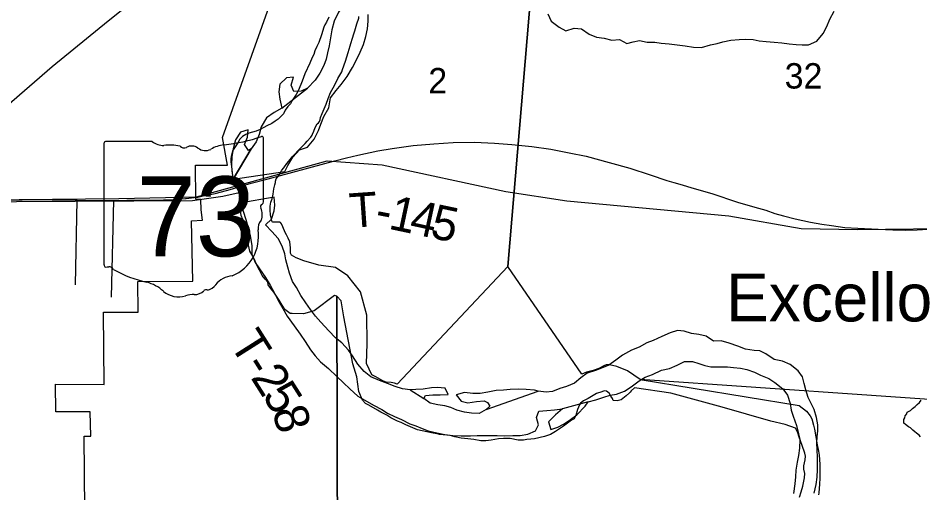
# Model space of a CAD drawing. Extents: x 0 to 34, y 0 to 22.
# Drawn here: x 3.596 to 5.086, y 14.655 to 15.439 of the extents above; entities that cross this region are included whole.
import ezdxf

# ---------------------------------------------------------------- set-up
doc = ezdxf.new("R2010")
doc.units = 0
for name, color, linetype in [('GM_X_City_Street', 7, 'Continuous'), ('GM_X_Corporation', 7, 'Continuous'), ('GM_X_Major_River', 7, 'Continuous'), ('GM_X_Minor_Lake', 7, 'Continuous'), ('GM_X_Minor_River', 7, 'Continuous'), ('GM_X_Rail_Line', 7, 'Continuous'), ('GM_X_Section_Text', 7, 'Continuous'), ('GM_X_State_Location', 7, 'Continuous'), ('GM_X_State_Route', 7, 'Continuous'), ('GM_X_State_Shield', 7, 'Continuous'), ('GM_X_Township_Road_Text', 7, 'Continuous'), ('GM_X_Unincorporated_Text', 7, 'Continuous')]:
    doc.layers.add(name, color=color, linetype=linetype)

msp = doc.modelspace()

# ---------------------------------------------------------------- linework, layer by layer
at = {"layer": 'GM_X_City_Street'}
for p, q in [((3.6909, 14.9987), (3.6938, 15.1382)), ((3.7507, 14.9784), (3.7543, 15.1377))]:
    msp.add_line(p, q, dxfattribs=at)
at = {"layer": 'GM_X_Corporation'}
for points in [[(4.4791, 15.9012), (4.4054, 15.0286), (4.2225, 14.8344), (4.218, 14.8364), (4.2127, 14.8373), (4.2044, 14.8382), (4.1987, 14.8402), (4.1875, 14.8465), (4.1808, 14.8501), (4.1717, 14.8688), (4.1731, 14.901), (4.1727, 14.9487), (4.1621, 14.9872), (4.1411, 15.0134), (4.1209, 15.0271), (4.093, 15.0311), (4.0681, 15.0381), (4.0558, 15.0429), (4.0479, 15.0473), (4.0461, 15.0507), (4.0463, 15.0598), (4.045, 15.0697), (4.0424, 15.0754), (4.0395, 15.0808), (4.0373, 15.085), (4.0338, 15.0945), (4.0312, 15.0991), (4.0297, 15.1014), (4.0286, 15.1022), (4.0275, 15.1022), (4.0233, 15.102), (4.0199, 15.1017), (4.0169, 15.1017), (4.0161, 15.1025), (4.0147, 15.1067), (4.0133, 15.1139), (4.0127, 15.1215), (4.0125, 15.1283), (4.0138, 15.1347), (4.0158, 15.1404), (4.0175, 15.1483), (4.0188, 15.157), (4.0205, 15.1634), (4.0213, 15.1672), (4.0217, 15.1698), (4.0229, 15.1732), (4.0272, 15.1791), (4.032, 15.1878), (4.0355, 15.1915), (4.0405, 15.1986), (4.046, 15.2053), (4.0491, 15.2097), (4.0518, 15.2123), (4.0604, 15.2216), (4.0708, 15.2316), (4.0739, 15.2357), (4.0797, 15.2424), (4.0821, 15.2454), (4.0829, 15.2473), (4.0849, 15.2518), (4.0873, 15.2582), (4.0904, 15.2641), (4.0927, 15.266), (4.0943, 15.2682), (4.0951, 15.2705), (4.096, 15.2746), (4.0984, 15.281), (4.1051, 15.2964), (4.1084, 15.3058), (4.1124, 15.3156), (4.1167, 15.3238), (4.1199, 15.3298), (4.1246, 15.3388), (4.1309, 15.35), (4.1325, 15.3538), (4.1374, 15.3673), (4.1418, 15.382), (4.1447, 15.3929), (4.1459, 15.3967), (4.1488, 15.4057), (4.1508, 15.4128), (4.1524, 15.4174), (4.1561, 15.429), (4.159, 15.4384), (4.1594, 15.4411)], [(2.1072, 14.098), (3.6049, 14.098), (3.6045, 14.5716), (3.634, 14.5656), (3.707, 14.5657), (3.7055, 14.7489), (3.7162, 14.7489), (3.7154, 14.7888), (3.6586, 14.7888), (3.6582, 14.8349), (3.7385, 14.8339), (3.7375, 14.9532), (3.7944, 14.9533), (3.7943, 15.0043), (3.8851, 15.0045), (3.883, 15.1039), (3.901, 15.1054), (3.8988, 15.1225), (3.8983, 15.1392), (3.8899, 15.1397), (3.8896, 15.1958), (3.9423, 15.1962), (3.9341, 15.2418), (4.0311, 15.5141)], [(4.1098, 15.4402), (4.1058, 15.432), (4.103, 15.4275), (4.1014, 15.4234), (4.0978, 15.411), (4.0929, 15.3986), (4.0901, 15.3918), (4.0866, 15.3847), (4.0846, 15.3787), (4.0822, 15.3734), (4.0782, 15.3644), (4.0699, 15.3464), (4.0654, 15.3344), (4.0594, 15.3197), (4.0559, 15.3126), (4.0492, 15.3029), (4.0461, 15.2973), (4.0418, 15.2928), (4.0375, 15.2865), (4.0347, 15.2805), (4.0305, 15.276), (4.0258, 15.2716), (4.0208, 15.2687), (4.0154, 15.2646), (4.0074, 15.2606), (3.9963, 15.2548), (3.9898, 15.2519), (3.9776, 15.2488), (3.9723, 15.2466), (3.9673, 15.2433), (3.9626, 15.2389), (3.9591, 15.2329), (3.954, 15.2243), (3.9505, 15.2194), (3.9488, 15.213), (3.9475, 15.207), (3.9478, 15.2013), (3.9494, 15.1895), (3.95, 15.1823), (3.9514, 15.1736), (3.9539, 15.1682), (3.9579, 15.159), (3.9604, 15.1537), (3.9615, 15.1503), (3.9348, 15.144), (3.8843, 15.1371), (3.1092, 15.1326)], [(4.1253, 14.098), (4.1226, 14.9801), (4.1192, 14.981), (4.0853, 14.9559), (4.0678, 14.9506), (4.0488, 14.951), (4.0458, 14.9511), (4.0369, 14.9577), (4.0274, 14.9735), (4.0186, 14.9865), (4.0141, 14.9927), (4.0097, 14.9988), (4.0087, 15.0027), (4.0046, 15.008), (3.9994, 15.0138), (3.9951, 15.023), (3.9907, 15.0311), (3.9878, 15.0376), (3.9842, 15.0456), (3.9791, 15.054), (3.9767, 15.0639), (3.9752, 15.0685), (3.9739, 15.0776), (3.9716, 15.0947), (3.9706, 15.0997), (3.9677, 15.1066), (3.9648, 15.1127), (3.9642, 15.1165), (3.964, 15.1263), (3.9646, 15.1373), (3.9636, 15.1438), (3.9615, 15.1503), (3.9348, 15.144), (3.8843, 15.1371), (3.1092, 15.1326)], [(4.8874, 14.6482), (4.8898, 14.6568), (4.8927, 14.6662), (4.8956, 14.6802), (4.8958, 14.6874), (4.8941, 14.6942), (4.8942, 14.6999), (4.8967, 14.7097), (4.8972, 14.7157), (4.8961, 14.7207), (4.8915, 14.7333), (4.8865, 14.7474), (4.884, 14.7558), (4.8804, 14.7623), (4.8634, 14.768), (4.8397, 14.7738), (4.7595, 14.7967), (4.6748, 14.8198), (4.6144, 14.8286), (4.609, 14.8238), (4.6074, 14.8216), (4.6066, 14.8201), (4.6008, 14.8153), (4.5927, 14.8087), (4.5859, 14.8069), (4.5795, 14.8078), (4.578, 14.8109), (4.5755, 14.8151), (4.5725, 14.8197), (4.5681, 14.8232), (4.5643, 14.8237), (4.5605, 14.8222), (4.5517, 14.819), (4.5379, 14.811), (4.5306, 14.807), (4.5256, 14.8033), (4.5236, 14.8003), (4.5204, 14.7928), (4.5176, 14.783), (4.5152, 14.7774), (4.5106, 14.7752), (4.4975, 14.7653), (4.484, 14.7565), (4.476, 14.7517), (4.4661, 14.7485), (4.4493, 14.7443), (4.4432, 14.7437), (4.4368, 14.7431), (4.4311, 14.7421), (4.4224, 14.7422), (4.4092, 14.7448), (4.3982, 14.745), (4.3898, 14.7445), (4.3841, 14.7431), (4.3777, 14.7421), (4.3689, 14.7411), (4.361, 14.7413), (4.3493, 14.7434), (4.3391, 14.7444), (4.3281, 14.7458), (4.3179, 14.7475), (4.31, 14.75), (4.293, 14.7515), (4.2927, 14.7518), (4.2908, 14.7519), (4.2795, 14.7544), (4.2561, 14.7595), (4.2369, 14.7674), (4.2294, 14.7714), (4.2231, 14.7738), (4.2118, 14.7793), (4.2055, 14.7833), (4.1968, 14.788), (4.1957, 14.7884), (4.1901, 14.7916), (4.1755, 14.8002), (4.1703, 14.8026), (4.1655, 14.8084), (4.159, 14.8225), (4.1557, 14.8465), (4.1493, 14.8682), (4.1347, 14.9458), (4.13, 14.9724), (4.1226, 14.9801), (4.1253, 14.098)], [(5.3881, 14.7897), (4.6238, 14.8425), (4.8869, 14.7997), (4.8988, 14.7903), (4.905, 14.7822), (4.9076, 14.7773), (4.9104, 14.767), (4.9121, 14.7605), (4.9142, 14.748), (4.9165, 14.7343), (4.9186, 14.724), (4.9196, 14.7175), (4.9207, 14.7024), (4.9209, 14.6921), (4.921, 14.6796), (4.92, 14.6694), (4.919, 14.6554), (4.9185, 14.652)]]:
    msp.add_lwpolyline(points, dxfattribs=at)
msp.add_lwpolyline([(4.4791, 15.9012), (5.4696, 15.8133), (5.3881, 14.7897), (4.6238, 14.8425), (4.6032, 14.8565), (4.5856, 14.8637), (4.5735, 14.8663), (4.5679, 14.8668), (4.5637, 14.865), (4.5556, 14.8606), (4.5464, 14.8574), (4.5354, 14.8542), (4.5274, 14.851), (4.4054, 15.0286)], close=True, dxfattribs=at)
at = {"layer": 'GM_X_Major_River'}
for p, q in [((4.0319, 15.2902), (4.0742, 15.3228)), ((3.9516, 15.1731), (3.9811, 15.2228)), ((3.9516, 15.1731), (4.037, 15.1856)), ((4.0195, 15.1432), (3.9627, 15.1334)), ((4.2439, 14.8255), (4.2666, 14.8109)), ((4.3698, 14.7929), (4.4553, 14.8229)), ((4.538, 14.8055), (4.4959, 14.7941))]:
    msp.add_line(p, q, dxfattribs=at)
for points in [[(4.1523, 15.5504), (4.1481, 15.538), (4.1565, 15.5256), (4.1565, 15.5127), (4.152, 15.4992), (4.1483, 15.4894), (4.1422, 15.4755), (4.1354, 15.462), (4.1255, 15.4482), (4.1183, 15.4333), (4.1145, 15.4193), (4.1127, 15.4091), (4.1103, 15.3928), (4.1077, 15.3815), (4.1052, 15.371), (4.1015, 15.3604), (4.095, 15.3477), (4.0871, 15.3361), (4.0742, 15.3228)], [(4.037, 15.1856), (4.0418, 15.1954), (4.0502, 15.2092), (4.0611, 15.2211), (4.0742, 15.2256), (4.0852, 15.2386), (4.0924, 15.2529), (4.0965, 15.2638), (4.1014, 15.2765), (4.1098, 15.2907), (4.1125, 15.307), (4.1216, 15.3193), (4.1302, 15.3289), (4.1401, 15.3423), (4.1485, 15.3573), (4.1557, 15.3708), (4.1613, 15.3824), (4.167, 15.3951), (4.1707, 15.4083), (4.1737, 15.4208), (4.1745, 15.4333), (4.1748, 15.4443)], [(4.0742, 15.3228), (4.0638, 15.3182), (4.052, 15.3174), (4.0474, 15.3281), (4.0515, 15.3409), (4.0398, 15.3401), (4.0288, 15.3297), (4.027, 15.3169), (4.0289, 15.3051), (4.0319, 15.2902)], [(4.0319, 15.2902), (4.0196, 15.2829), (4.0068, 15.2738), (3.9976, 15.2592), (3.9943, 15.2468), (3.9898, 15.2347), (3.9811, 15.2228)], [(3.9811, 15.2228), (3.9768, 15.2203), (3.9703, 15.2303), (3.9752, 15.2424), (3.9762, 15.2541), (3.9636, 15.2506), (3.9557, 15.2376), (3.9515, 15.2229), (3.9496, 15.2096), (3.9488, 15.1964), (3.9493, 15.1861), (3.9516, 15.1731)], [(3.9811, 15.2228), (3.9516, 15.1731)], [(4.2439, 14.8255), (4.2314, 14.827), (4.219, 14.8308), (4.2066, 14.836), (4.1934, 14.8405), (4.1792, 14.847), (4.168, 14.8557), (4.1573, 14.8677), (4.1486, 14.8812), (4.142, 14.8909), (4.1313, 14.903), (4.1209, 14.9112), (4.1095, 14.9225), (4.0962, 14.9369), (4.0874, 14.947), (4.0793, 14.9579), (4.0716, 14.9687), (4.0636, 14.9811), (4.056, 14.9942), (4.0498, 15.0042), (4.0445, 15.018), (4.0418, 15.0276), (4.0387, 15.0398), (4.037, 15.0497), (4.0325, 15.0624), (4.026, 15.0751), (4.0153, 15.0864), (4.005, 15.0977), (4.0151, 15.1069), (4.0196, 15.1204), (4.0203, 15.1299), (4.0195, 15.1432)], [(3.9627, 15.1334), (3.9684, 15.1199), (3.9725, 15.1061), (3.9764, 15.0931), (3.9798, 15.0801), (3.9824, 15.063), (3.9827, 15.0493), (3.9881, 15.0355), (3.995, 15.0251), (4.0052, 15.0107), (4.0125, 14.998), (4.0197, 14.9849), (4.0262, 14.9726), (4.0334, 14.9595), (4.041, 14.9468), (4.0524, 14.9309), (4.0622, 14.917), (4.0706, 14.905), (4.0794, 14.8914), (4.0871, 14.8814), (4.0959, 14.8713), (4.1093, 14.8607), (4.123, 14.8474), (4.1341, 14.8368), (4.1444, 14.8271), (4.1574, 14.8149), (4.169, 14.8082), (4.1836, 14.7998), (4.197, 14.7926), (4.2067, 14.7867), (4.218, 14.7814), (4.2296, 14.7762), (4.2435, 14.7694), (4.2532, 14.7657), (4.2641, 14.7616), (4.2739, 14.7579), (4.2882, 14.7541), (4.3011, 14.7515), (4.3147, 14.75), (4.3284, 14.7492), (4.3436, 14.7496), (4.3549, 14.7497), (4.3739, 14.7499), (4.388, 14.7499), (4.4005, 14.7496), (4.4134, 14.75), (4.426, 14.7497), (4.4385, 14.752), (4.4509, 14.7577), (4.4561, 14.7678), (4.4526, 14.7797), (4.4563, 14.7902), (4.4696, 14.791), (4.4822, 14.7922), (4.4959, 14.7941)], [(4.9117, 14.655), (4.9147, 14.6693), (4.9165, 14.6811), (4.9169, 14.6936), (4.9168, 14.7038), (4.9167, 14.7148), (4.9163, 14.7255), (4.9159, 14.7384), (4.9165, 14.7479), (4.9175, 14.7577), (4.9174, 14.7676), (4.9155, 14.7794), (4.9113, 14.7928), (4.9066, 14.8028), (4.9016, 14.8124), (4.8974, 14.8254), (4.895, 14.8358), (4.8919, 14.8465), (4.8849, 14.8565), (4.8719, 14.8671), (4.8592, 14.8724), (4.8452, 14.8754), (4.8314, 14.8845), (4.8217, 14.8897), (4.8122, 14.89), (4.7982, 14.8923), (4.7851, 14.8972), (4.7712, 14.9021), (4.758, 14.9063), (4.7454, 14.9055), (4.7328, 14.9141), (4.7207, 14.9164), (4.7086, 14.9182), (4.6969, 14.9223), (4.6859, 14.923), (4.6737, 14.9191), (4.6598, 14.9134), (4.6456, 14.9066), (4.6352, 14.9027), (4.6225, 14.8958), (4.6098, 14.8905), (4.5948, 14.8825), (4.5836, 14.8745), (4.5723, 14.8661), (4.56, 14.8611), (4.5504, 14.8572), (4.5366, 14.853), (4.5258, 14.8449), (4.5153, 14.8361), (4.5022, 14.8307), (4.4915, 14.8276), (4.4792, 14.8226), (4.4689, 14.8214), (4.4553, 14.8229)], [(4.538, 14.8055), (4.551, 14.8086), (4.564, 14.8131), (4.5744, 14.8163), (4.5847, 14.8183), (4.5981, 14.8229), (4.6089, 14.8305), (4.6225, 14.84), (4.6325, 14.8462), (4.6444, 14.8508), (4.659, 14.8577), (4.6724, 14.8607), (4.6851, 14.8661), (4.6974, 14.8718), (4.7103, 14.8719), (4.7209, 14.8689), (4.7306, 14.8652), (4.7405, 14.8631), (4.7545, 14.8631), (4.7682, 14.8631), (4.778, 14.8621), (4.7898, 14.861), (4.8003, 14.8588), (4.8131, 14.8543), (4.8229, 14.8495), (4.8368, 14.8442), (4.8464, 14.8374), (4.8595, 14.8272), (4.8671, 14.8164), (4.8717, 14.803), (4.8737, 14.7919), (4.8768, 14.7816), (4.8825, 14.7662), (4.8855, 14.7529), (4.8875, 14.7433), (4.8871, 14.7293), (4.8853, 14.7172), (4.8831, 14.7059), (4.8812, 14.6926), (4.8805, 14.6816), (4.8794, 14.6703), (4.8771, 14.6544)], [(4.2694, 14.8161), (4.2816, 14.8169), (4.2934, 14.817), (4.3067, 14.8178), (4.302, 14.8278), (4.2888, 14.8289), (4.2793, 14.8288), (4.2656, 14.8265), (4.2534, 14.826), (4.2439, 14.8255)], [(4.4553, 14.8229), (4.4493, 14.8246), (4.4356, 14.8257), (4.4228, 14.8264), (4.4091, 14.8257), (4.398, 14.8248), (4.3859, 14.824), (4.3725, 14.8217), (4.3599, 14.8194), (4.3474, 14.8193), (4.3337, 14.8208), (4.32, 14.817), (4.328, 14.8066), (4.3393, 14.8036), (4.3538, 14.8059), (4.366, 14.8074)], [(4.2666, 14.8109), (4.2694, 14.8161)], [(4.3698, 14.7929), (4.3579, 14.7864), (4.3453, 14.7867), (4.334, 14.7882), (4.3212, 14.7916), (4.3114, 14.7964), (4.3012, 14.7989), (4.2895, 14.8008), (4.2771, 14.8034), (4.2666, 14.8109)], [(4.366, 14.8074), (4.3716, 14.8043), (4.3756, 14.7981), (4.3698, 14.7929)], [(4.4959, 14.7941), (4.4839, 14.7838), (4.4725, 14.7727), (4.4764, 14.7597), (4.4879, 14.7636), (4.4975, 14.7686), (4.5091, 14.7763), (4.5196, 14.784), (4.5329, 14.7984), (4.538, 14.8055)]]:
    msp.add_lwpolyline(points, dxfattribs=at)
at = {"layer": 'GM_X_Minor_Lake'}
msp.add_lwpolyline([(4.4714, 15.4458), (4.4771, 15.4335), (4.4901, 15.4237), (4.5014, 15.4177), (4.5148, 15.4219), (4.5269, 15.4211), (4.5399, 15.4121), (4.552, 15.4072), (4.5644, 15.4057), (4.5769, 15.402), (4.5898, 15.4031), (4.6018, 15.3967), (4.6125, 15.3995), (4.6228, 15.4019), (4.6356, 15.3989), (4.6482, 15.3989), (4.6588, 15.3975), (4.6717, 15.3964), (4.6853, 15.3945), (4.6985, 15.393), (4.7121, 15.3904), (4.7254, 15.39), (4.74, 15.3945), (4.751, 15.3969), (4.7606, 15.3997), (4.774, 15.402), (4.7877, 15.4031), (4.7983, 15.404), (4.8108, 15.4033), (4.8206, 15.4011), (4.8324, 15.4), (4.8453, 15.3989), (4.8578, 15.3978), (4.8702, 15.3964), (4.8816, 15.3953), (4.8918, 15.3946), (4.9021, 15.3947), (4.9156, 15.4008), (4.9261, 15.4131), (4.9322, 15.4247), (4.9371, 15.4371), (4.9446, 15.4498)], dxfattribs=at)
at = {"layer": 'GM_X_Minor_River'}
msp.add_lwpolyline([(5.0869, 14.7478), (5.0847, 14.7506), (5.0807, 14.7538), (5.0777, 14.7562), (5.0744, 14.7589), (5.0707, 14.7625), (5.0673, 14.7642), (5.0625, 14.7681), (5.0596, 14.7705), (5.0598, 14.7762), (5.061, 14.7792), (5.0615, 14.7823), (5.0643, 14.7856), (5.0652, 14.7882), (5.0703, 14.7914), (5.0738, 14.7944), (5.0785, 14.7976), (5.0817, 14.8009), (5.0852, 14.8042), (5.0884, 14.8083)], dxfattribs=at)
at = {"layer": 'GM_X_Rail_Line'}
for points in [[(3.3781, 15.1371), (3.7625, 15.1411), (3.8908, 15.1437), (4.1071, 15.2029), (4.1979, 15.1964), (4.4021, 15.1525), (4.503, 15.1372), (4.7705, 15.1123), (4.89, 15.0915), (4.9836, 15.0897), (5.1669, 15.0922), (5.1739, 15.0968), (5.1979, 15.3351), (5.2386, 15.6999)], [(2.1, 14.3391), (2.5015, 14.5477), (2.6602, 14.6297), (2.7404, 14.6679), (2.8356, 14.7212), (2.8845, 14.7498), (2.9315, 14.7815), (2.9735, 14.8123), (3.0395, 14.8654), (3.1402, 14.9454), (3.2994, 15.0726), (3.3783, 15.1366), (3.5398, 15.2612), (3.6524, 15.359), (3.745, 15.434), (3.8337, 15.5051)]]:
    msp.add_lwpolyline(points, dxfattribs=at)
at = {"layer": 'GM_X_State_Route'}
for p, q in [((3.8825, 15.1419), (3.892, 15.143)), ((3.9018, 15.1455), (3.9219, 15.1492))]:
    msp.add_line(p, q, dxfattribs=at)
for points in [[(4.1089, 15.2003), (4.1195, 15.2032), (4.1389, 15.2083), (4.1575, 15.2124), (4.1908, 15.2197), (4.2145, 15.2235), (4.2491, 15.2282), (4.2831, 15.2314), (4.3149, 15.2331), (4.3501, 15.2338), (4.3833, 15.2321), (4.4121, 15.2303), (4.445, 15.2267), (4.4766, 15.2224), (4.5069, 15.2165), (4.5349, 15.2109), (4.5727, 15.2006), (4.6071, 15.191), (4.6406, 15.1801), (4.6678, 15.1707), (4.6796, 15.1675)], [(3.9219, 15.1492), (3.9239, 15.1495), (3.9468, 15.1559), (3.9665, 15.1621), (3.9813, 15.1661), (4.0092, 15.1735), (4.0705, 15.1898), (4.1089, 15.2003)], [(4.6796, 15.1675), (4.6895, 15.1648), (4.713, 15.1575), (4.7421, 15.1492), (4.785, 15.1351), (4.8134, 15.1265), (4.8318, 15.1216), (4.8465, 15.1161), (4.8606, 15.1124), (4.8801, 15.1075), (4.8927, 15.1046)], [(3.5595, 15.1374), (3.5614, 15.1375), (3.6028, 15.1388), (3.627, 15.1391), (3.6527, 15.1388), (3.6938, 15.1382), (3.733, 15.1378), (3.7543, 15.1377), (3.7553, 15.1377)], [(3.7553, 15.1377), (3.7761, 15.1381), (3.7931, 15.1382), (3.8158, 15.1383), (3.8363, 15.1386), (3.8551, 15.1395), (3.8729, 15.1408)], [(3.8729, 15.1408), (3.8739, 15.1408), (3.8825, 15.1419)], [(3.892, 15.143), (3.893, 15.1431), (3.9018, 15.1455)], [(4.8927, 15.1046), (4.9053, 15.1018), (4.9239, 15.0986), (4.9403, 15.0962), (4.9619, 15.0932), (4.9835, 15.0921), (5.0174, 15.0904), (5.0413, 15.0894), (5.0625, 15.0889), (5.0815, 15.0894), (5.1088, 15.0909), (5.1254, 15.0917)]]:
    msp.add_lwpolyline(points, dxfattribs=at)
at = {"layer": 'GM_X_State_Shield'}
for p, q in [((3.7382, 15.2315), (3.7382, 15.0314)), ((3.818, 15.2349), (3.7408, 15.2349)), ((4.0019, 15.1352), (4.0019, 15.2399)), ((4.0018, 15.1352), (4.0019, 15.1352))]:
    msp.add_line(p, q, dxfattribs=at)
for centre, radius, start, end in [((3.908, 15.5078), 0.2796, 275.8445, 288.9065), ((3.9989, 15.2403), 0.00294, 351.8621, 97.738), ((3.7412, 15.2319), 0.00305, 98.1301, 188.1301), ((3.8364, 15.2582), 0.0296, 231.6195, 271.1119), ((3.8462, 15.1226), 0.1064, 80.4867, 94.9883), ((3.9436, 15.1738), 0.0563, 97.3462, 120.7689), ((3.8704, 15.2329), 0.00855, 219.7921, 297.1024), ((3.8829, 15.2098), 0.0178, 54.4667, 119.1411), ((3.9059, 15.2415), 0.0214, 233.8562, 294.8282), ((4.0012, 15.1275), 0.00454, 107.944, 210.337), ((3.9723, 15.1143), 0.0273, 340.033, 23.6496), ((3.9987, 15.1348), 0.00314, 289.6038, 7.7341), ((4.0124, 15.0914), 0.0198, 136.8065, 186.9296), ((3.9236, 15.0781), 0.0699, 292.3089, 8.9858), ((3.7413, 15.0309), 0.00308, 171.9584, 258.3066), ((3.7417, 15.0514), 0.0235, 267.339, 280.6039), ((3.7465, 15.0198), 0.00848, 29.7484, 93.2717), ((3.8536, 15.1996), 0.2019, 240.4129, 257.1985), ((3.9531, 14.9752), 0.0383, 94.4031, 142.5768), ((3.7934, 14.9415), 0.0632, 47.1842, 75.836), ((3.9071, 14.9845), 0.00601, 65.7517, 132.6484), ((3.9046, 15.012), 0.0226, 282.8732, 323.2771), ((3.8617, 15.0188), 0.0401, 230.7004, 286.2918), ((3.8849, 14.9496), 0.0329, 85.6951, 111.2099), ((3.8878, 15.0038), 0.0214, 268.777, 315.5493)]:
    msp.add_arc(centre, radius, start, end, dxfattribs=at)

# ---------------------------------------------------------------- texts
at = {"layer": 'GM_X_Section_Text'}
for s, height, p in [('32', 0.04186, (4.8627, 15.3224)), ('2', 0.0419, (4.274, 15.3144))]:
    msp.add_text(s, height=height, rotation=0, dxfattribs=at).set_placement(p)
at = {"layer": 'GM_X_State_Location'}
for s in ['s', 'r']:
    msp.add_text(s, height=0.000189, dxfattribs=at).set_placement((3.8671, 15.1181))
msp.add_text('73', height=0.000189, rotation=0, dxfattribs=at).set_placement((3.8194, 15.1043))
at = {"layer": 'GM_X_State_Shield'}
msp.add_text('73', height=0.13184, dxfattribs=at).set_placement((3.7919, 15.0455))
at = {"layer": 'GM_X_Township_Road_Text'}
for s, rotation, p in [('T', 4.0275, (4.1454, 15.0925)), ('1', 347.9578, (4.2065, 15.0914)), ('4', 347.7929, (4.2407, 15.0841)), ('5', 348.1418, (4.2753, 15.0767)), ('-', 349.2588, (4.1839, 15.0957)), ('T', 302.3397, (3.9444, 14.9013)), ('-', 302.3539, (3.9671, 14.8654)), ('2', 302.3771, (3.9796, 14.8456)), ('5', 302.5115, (3.9985, 14.816)), ('8', 286.4515, (4.0155, 14.7903))]:
    msp.add_text(s, height=0.0568, rotation=rotation, dxfattribs=at).set_placement(p)
at = {"layer": 'GM_X_Unincorporated_Text'}
msp.add_text('Excello', height=0.07898, rotation=0, dxfattribs=at).set_placement((4.766, 14.9382))

doc.saveas('drawing.dxf')
